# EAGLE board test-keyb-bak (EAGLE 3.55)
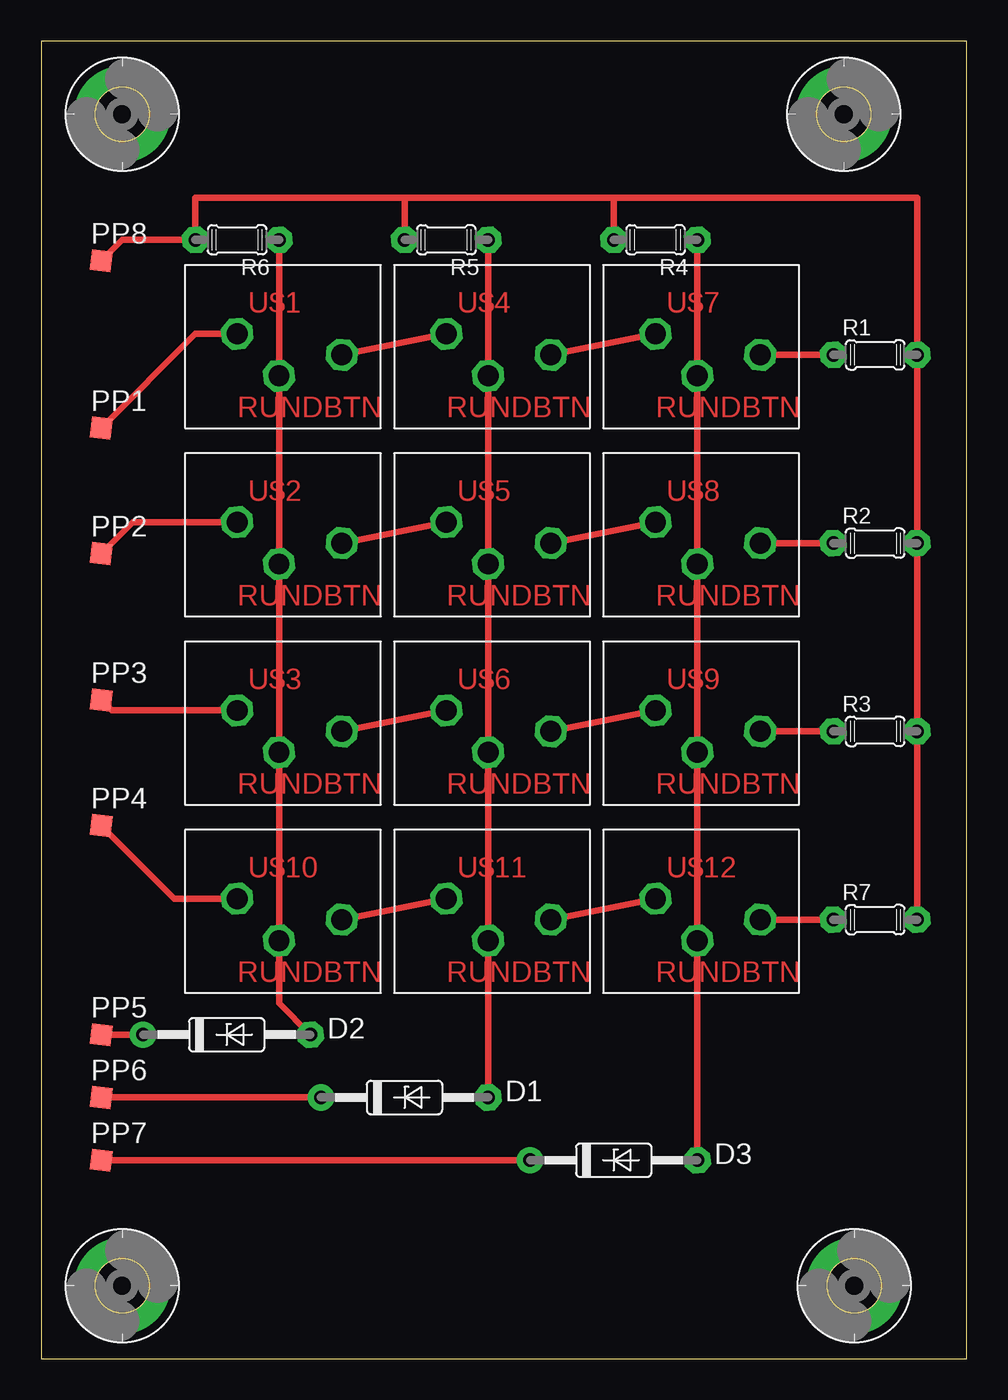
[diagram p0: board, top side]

Size 56.19 x 80 mm. Coordinates in mm from the lower left corner, seen from the top.
Outline: 0,0 56.19,0 56.19,80 0,80 0,0
Copper layers used: Top

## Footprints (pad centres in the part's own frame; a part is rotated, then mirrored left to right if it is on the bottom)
35Z10 = drill 0.813 pad 1.6 round:  -5.08,0 | drill 0.813 pad 1.6 octagon:  5.08,0
3,3-P = drill 3.302 pad 5.842 round: 3 0,0
,27 = smd 1.27 x 1.27 rotated 7:  0,0
04/5 = drill 0.813 pad 1.6 octagon:  -2.54,0;  2.54,0
NDBTN = drill 1.27 pad 1.676 octagon:  3.175,-0.635;  -0.635,-1.905;  -3.175,0.635

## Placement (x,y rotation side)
D1  1N821  [35Z10]  22.06,15.87 0 top
D2  1N821  [35Z10]  11.27,19.68 0 top
D3  1N821  [35Z10]  34.76,12.06 0 top
PAD1  BO3,3P  [3,3-P]  4.92,4.44 0 top
PAD2  BO3,3P  [3,3-P]  49.37,4.44 0 top
PAD3  BO3,3P  [3,3-P]  48.73,75.56 0 top
PAD4  BO3,3P  [3,3-P]  4.92,75.56 0 top
PP1  B1,27  [,27]  3.64,56.51 0 top
PP2  B1,27  [,27]  3.64,48.89 0 top
PP3  B1,27  [,27]  3.64,40 0 top
PP4  B1,27  [,27]  3.64,32.38 0 top
PP5  B1,27  [,27]  3.64,19.68 0 top
PP6  B1,27  [,27]  3.64,15.87 0 top
PP7  B1,27  [,27]  3.64,12.06 0 top
PP8  B1,27  [,27]  3.64,66.67 0 top
R1  0204/5  [04/5]  50.64,60.96 0 top
R2  0204/5  [04/5]  50.64,49.53 0 top
R3  0204/5  [04/5]  50.64,38.1 0 top
R4  0204/5  [04/5]  37.3,67.94 180 top
R5  0204/5  [04/5]  24.6,67.94 180 top
R6  0204/5  [04/5]  11.9,67.94 180 top
R7  0204/5  [04/5]  50.64,26.66 0 top
U$1  RUNDBTN  [NDBTN]  15.08,61.59 0 top
U$2  RUNDBTN  [NDBTN]  15.08,50.16 0 top
U$3  RUNDBTN  [NDBTN]  15.08,38.73 0 top
U$4  RUNDBTN  [NDBTN]  27.77,61.59 0 top
U$5  RUNDBTN  [NDBTN]  27.77,50.16 0 top
U$6  RUNDBTN  [NDBTN]  27.77,38.73 0 top
U$7  RUNDBTN  [NDBTN]  40.48,61.59 0 top
U$8  RUNDBTN  [NDBTN]  40.48,50.16 0 top
U$9  RUNDBTN  [NDBTN]  40.48,38.73 0 top
U$10  RUNDBTN  [NDBTN]  15.08,27.3 0 top
U$11  RUNDBTN  [NDBTN]  27.77,27.3 0 top
U$12  RUNDBTN  [NDBTN]  40.48,27.3 0 top

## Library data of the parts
D1-D3 = diode
PAD1-PAD4 = holes
PP1-PP8 = testpad
R1-R7 = r
U$1-U$12 = buttons

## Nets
N$1: U$6. U$9.
N$2: PP8. R1. R2. R3. R4. R5. R6. R7.
N$3: D1. R5. U$4. U$5. U$6. U$11.
N$4: PP1. U$1.
N$5: U$1. U$4.
N$6: U$4. U$7.
N$7: R1. U$7.
N$8: PP2. U$2.
N$9: PP3. U$3.
N$10: PP4. U$10.
N$11: U$2. U$5.
N$12: D3. PP7.
N$13: U$3. U$6.
N$14: U$5. U$8.
N$15: U$10. U$11.
N$16: U$11. U$12.
N$17: R7. U$12.
N$18: R3. U$9.
N$19: R2. U$8.
N$20: D2. R6. U$1. U$2. U$3. U$10.
N$21: D1. PP6.
N$22: D2. PP5.
N$23: D3. R4. U$7. U$8. U$9. U$12.

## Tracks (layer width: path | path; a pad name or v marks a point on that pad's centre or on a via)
N$1
  Top 0.406: 30.95,38.1 U$9.
N$2
  Top 0.406: R7. R3. R2. R1. 53.18,70.48 34.76,70.48 | 34.76,70.48 R4. | 22.06,70.48 34.76,70.48 | 22.06,70.48 R5. | 22.06,70.48 9.36,70.48 R6. 4.92,67.94 PP8.
N$3
  Top 0.406: D1. 27.14,25.39 27.14,36.83 27.14,48.26 27.14,59.69 27.14,67.94
N$4
  Top 0.406: U$1. 9.36,62.23 PP1.
N$5
  Top 0.406: 18.25,60.96 U$4.
N$6
  Top 0.406: 30.95,60.96 U$7.
N$7
  Top 0.406: 43.65,60.96 48.09,60.96
N$8
  Top 0.406: U$2. 5.55,50.8 PP2.
N$9
  Top 0.406: U$3. 4.28,39.37 PP3.
N$10
  Top 0.406: U$10. 8.09,27.93 PP4.
N$11
  Top 0.406: 18.25,49.53 U$5.
N$12
  Top 0.406: PP7. 29.68,12.06
N$13
  Top 0.406: 18.25,38.1 U$6.
N$14
  Top 0.406: 30.95,49.53 U$8.
N$15
  Top 0.406: 18.25,26.66 U$11.
N$16
  Top 0.406: 30.95,26.66 U$12.
N$17
  Top 0.406: 43.65,26.66 48.09,26.66
N$18
  Top 0.406: 43.65,38.1 48.09,38.1
N$19
  Top 0.406: 43.65,49.53 48.09,49.53
N$20
  Top 0.406: 14.44,67.94 14.44,59.69 14.44,48.26 14.44,36.83 14.44,25.39 14.44,21.58 D2.
N$21
  Top 0.406: PP6. 16.98,15.87
N$22
  Top 0.406: PP5. 6.19,19.68
N$23
  Top 0.406: D3. 39.84,25.39 39.84,36.83 39.84,48.26 39.84,59.69 39.84,67.94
